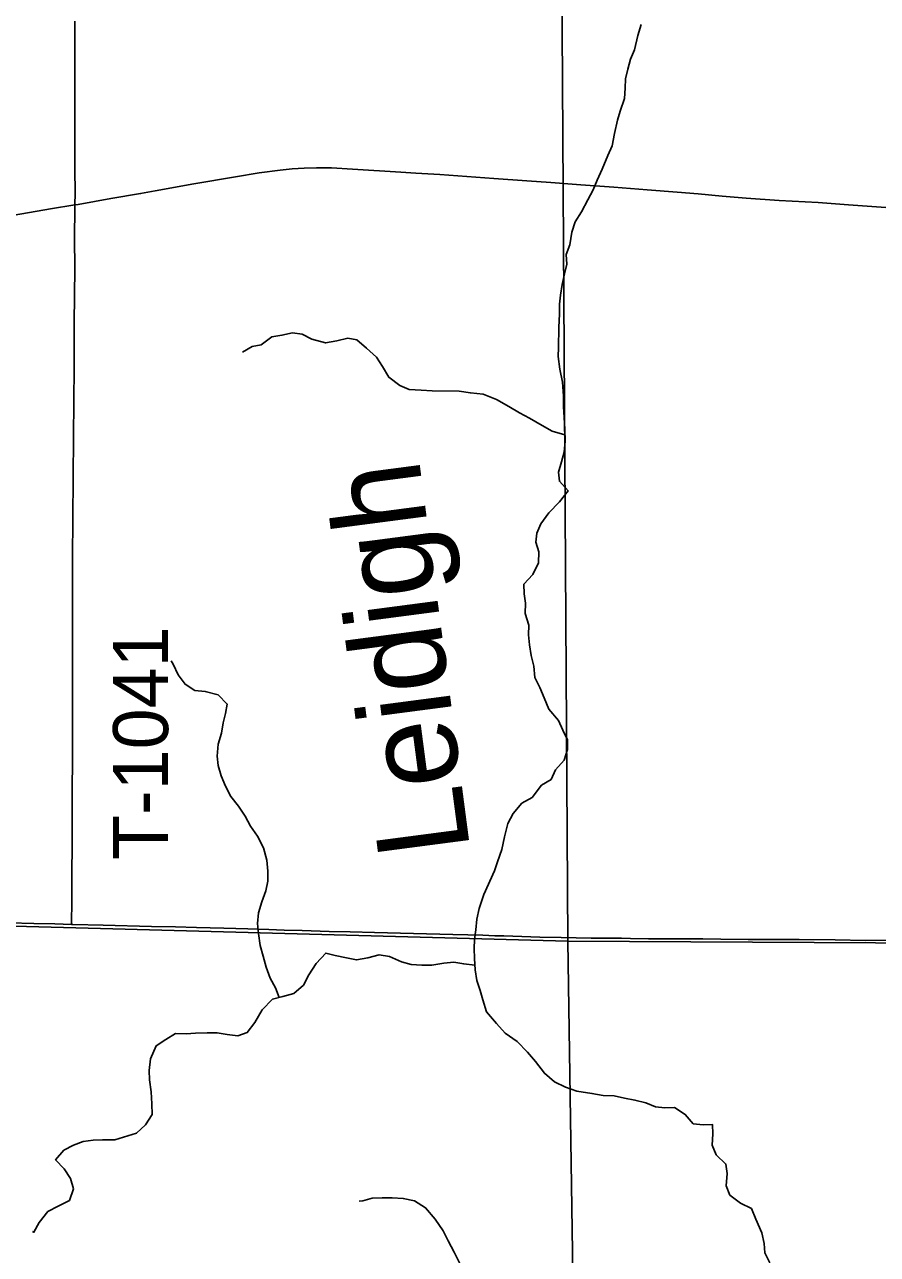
# Model space of a CAD drawing. Extents: x 1874609 to 2204689, y 815661 to 1281160.
# Drawn here: x 2015153 to 2019795, y 1076369 to 1083063 of the extents above; entities that cross this region are included whole.
import ezdxf

# ---------------------------------------------------------------- set-up
doc = ezdxf.new("R2010")
doc.units = 0
for name, color, linetype in [('GM_X_County_Road', 7, 'Continuous'), ('GM_X_Minor_River', 7, 'Continuous'), ('GM_X_Minor_River_Text', 7, 'Continuous'), ('GM_X_Section', 7, 'Continuous'), ('GM_X_Township_Road', 7, 'Continuous'), ('GM_X_Township_Road_Text', 7, 'Continuous')]:
    doc.layers.add(name, color=color, linetype=linetype)

msp = doc.modelspace()

# ---------------------------------------------------------------- linework, layer by layer
at = {"layer": 'GM_X_County_Road'}
for points in [[(2015426.8, 1082081.6), (2015444.7, 1082084.7), (2015622.4, 1082116), (2015784.2, 1082143.6), (2015862.9, 1082157.9), (2016074.7, 1082196.4), (2016301.2, 1082234.7), (2016430.8, 1082255.6), (2016544.6, 1082271.8), (2016610, 1082278.5), (2016675.7, 1082282.5), (2016741.5, 1082284.1), (2016823.7, 1082282.8), (2016938.6, 1082277.1), (2017200.6, 1082260.3), (2017282.4, 1082255.1), (2017413.3, 1082246.6), (2017707.2, 1082224.9), (2017886.9, 1082212.5), (2018017.7, 1082203.1), (2018181.4, 1082191), (2018361.4, 1082178.2), (2018541.3, 1082163.9), (2018704.8, 1082151.5), (2018819.1, 1082141.6), (2018949.7, 1082129.7), (2019080.4, 1082118.5), (2019260.4, 1082106.6), (2019473.5, 1082094.9), (2019637.2, 1082082.7), (2019866.3, 1082065.9)], [(2012702.2, 1081362.5), (2012708, 1081367.4), (2012721.2, 1081376.2), (2012749.7, 1081391.3), (2012779.6, 1081403.9), (2012825.6, 1081420.9), (2012949.6, 1081463.4), (2013150.5, 1081534.9), (2013366.6, 1081612.4), (2013706.1, 1081734.5), (2013830.1, 1081776.8), (2013923.9, 1081806), (2014018.5, 1081832.2), (2014098.2, 1081850.8), (2014226.9, 1081875.3), (2014420.6, 1081909.8), (2014614.7, 1081942.3), (2014970.1, 1082004), (2015293.3, 1082059.6), (2015426.8, 1082081.6)]]:
    msp.add_lwpolyline(points, dxfattribs=at)
at = {"layer": 'GM_X_Minor_River'}
for points in [[(2017919.3, 1080070.8), (2017949.7, 1080132.8), (2017952, 1080193), (2017936.2, 1080245.3), (2017940.5, 1080295.4), (2017962.8, 1080345.5), (2018007.2, 1080405.4), (2018065.6, 1080465.2), (2018112, 1080525.1), (2018064.2, 1080577.6), (2018058.5, 1080627.8), (2018074.8, 1080683.9), (2018091.1, 1080736), (2018095.4, 1080796.2), (2018093.7, 1080860.4), (2018090.1, 1080924.6), (2018086.4, 1080984.9), (2018086.7, 1081041.1), (2018081.1, 1081117.4), (2018067.4, 1081187.7), (2018057.7, 1081256), (2018060, 1081306.2), (2018060.6, 1081414.5), (2018065, 1081488.8), (2018065.3, 1081540.9), (2018069.5, 1081591.1), (2018079.9, 1081649.2), (2018092.2, 1081707.3), (2018104.5, 1081759.4), (2018100.8, 1081811.6), (2018121.1, 1081863.7), (2018131.4, 1081933.9), (2018149.8, 1081989.9), (2018184.1, 1082043.9), (2018218.5, 1082109.9), (2018248.9, 1082163.9), (2018269.2, 1082216), (2018297.5, 1082276), (2018328, 1082350.1), (2018352.3, 1082404.1), (2018364.7, 1082470.2), (2018381.1, 1082542.4), (2018395.4, 1082592.5), (2018417.8, 1082660.6), (2018422.1, 1082716.7), (2018424.4, 1082768.9), (2018436.7, 1082821), (2018451, 1082875.1), (2018473.3, 1082925.1), (2018491.7, 1083003.3), (2018510.1, 1083063.4)], [(2018094.5, 1080830.7), (2018025.6, 1080850.8), (2017969.6, 1080881.3), (2017901.7, 1080921.8), (2017847.8, 1080950.3), (2017789.8, 1080984.8), (2017721.9, 1081023.4), (2017649.9, 1081051.9), (2017579.8, 1081058.4), (2017517.8, 1081068.8), (2017371.5, 1081069.8), (2017311.4, 1081074.2), (2017247.3, 1081076.6), (2017195.4, 1081099), (2017135.5, 1081143.5), (2017101.7, 1081201.9), (2017067.9, 1081252.3), (2017014.1, 1081302.9), (2016962.2, 1081347.3), (2016912.2, 1081355.7), (2016852, 1081342), (2016791.8, 1081330.4), (2016715.8, 1081350.9), (2016663.9, 1081377.4), (2016611.8, 1081385.7), (2016553.6, 1081372.1), (2016499.5, 1081364.4), (2016441.2, 1081320.6), (2016391, 1081310.9), (2016338.8, 1081281.1)], [(2019209.9, 1076323.8), (2019182.1, 1076378.1), (2019178.4, 1076428.3), (2019166.7, 1076486.6), (2019133, 1076561.1), (2019109.2, 1076619.4), (2019049.3, 1076647.9), (2018991.4, 1076692.4), (2018971.6, 1076742.7), (2018978, 1076808.9), (2018970.3, 1076861.1), (2018918.4, 1076911.6), (2018896.7, 1076964), (2018899, 1077026.1), (2018897.3, 1077076.3), (2018847.2, 1077074.6), (2018793.1, 1077079), (2018749.3, 1077131.5), (2018691.4, 1077168), (2018637.3, 1077166.3), (2018587.2, 1077172.6), (2018535.3, 1077195.1), (2018475.2, 1077209.5), (2018419.2, 1077219.9), (2018363.1, 1077232.3), (2018303, 1077234.7), (2018241, 1077245.1), (2018158.9, 1077257.7), (2018096.9, 1077280.2), (2018037, 1077308.6), (2017983.1, 1077355.1), (2017933.3, 1077419.7), (2017891.5, 1077470.1), (2017833.7, 1077528.7), (2017769.9, 1077573.2), (2017722.1, 1077625.7), (2017668.3, 1077690.3), (2017646.6, 1077754.6), (2017632.8, 1077804.9), (2017615.1, 1077859.2), (2017605.4, 1077917.5), (2017601.7, 1077979.7), (2017600, 1078033.9), (2017602.3, 1078084.1), (2017608.5, 1078136.2), (2017614.9, 1078194.3), (2017627.2, 1078252.5), (2017653.6, 1078328.6), (2017710.4, 1078456.6), (2017726.7, 1078506.7), (2017751.1, 1078572.8), (2017765.5, 1078642.9), (2017783.9, 1078715), (2017812.2, 1078769.1), (2017860.6, 1078824.9), (2017916.9, 1078856.7), (2017967.3, 1078922.6), (2018019.6, 1078954.3), (2018043.9, 1079006.4), (2018090.3, 1079060.2), (2018108.6, 1079118.3), (2018108.9, 1079170.5), (2018083.1, 1079222.9), (2018059.3, 1079275.2), (2018007.6, 1079337.7), (2017981.8, 1079398.1), (2017958.1, 1079454.4), (2017930.3, 1079508.8), (2017924.7, 1079571.1), (2017910.9, 1079629.3), (2017901.2, 1079687.6), (2017895.5, 1079741.8), (2017897.8, 1079794), (2017878.1, 1079858.3), (2017880.4, 1079914.5), (2017872.6, 1079964.8), (2017870.9, 1080016.9), (2017919.3, 1080070.8)], [(2016539.1, 1077768.2), (2016518.9, 1077820.1), (2016489.1, 1077872.5), (2016467.4, 1077932.8), (2016451.7, 1077993.1), (2016436, 1078051.4), (2016426.3, 1078115.7), (2016420.6, 1078169.9), (2016426.9, 1078228.1), (2016445.2, 1078288.2), (2016465.6, 1078348.2), (2016477.9, 1078400.3), (2016476.2, 1078454.5), (2016472.5, 1078514.8), (2016452.8, 1078583.1), (2016421.1, 1078645.5), (2016383.3, 1078700), (2016353.5, 1078754.3), (2016317.8, 1078808.8), (2016276, 1078861.2), (2016246.2, 1078917.6), (2016222.5, 1078973.9), (2016206.7, 1079030.2), (2016201, 1079080.4), (2016207.3, 1079146.6), (2016225.7, 1079206.7), (2016234, 1079262.8), (2016246.3, 1079312.9), (2016256.6, 1079365.1), (2016206.7, 1079415.6), (2016136.7, 1079434.1), (2016080.6, 1079438.4), (2016026.7, 1079472.9), (2015988.9, 1079523.3), (2015961.2, 1079581.7), (2015951.3, 1079599.8)], [(2017603.8, 1077943.9), (2017543.4, 1077950), (2017489.4, 1077960.3), (2017435.3, 1077954.7), (2017369.1, 1077943.1), (2017315, 1077943.4), (2017256.9, 1077947.8), (2017204.9, 1077962.2), (2017138.9, 1077990.7), (2017082.9, 1077999.1), (2017020.7, 1077983.4), (2016960.5, 1077971.8), (2016904.5, 1077984.2), (2016844.4, 1077996.6), (2016792.4, 1078009), (2016740, 1077953.1), (2016699.6, 1077891.2), (2016671.3, 1077835.2), (2016618.9, 1077789.4), (2016558.7, 1077773.7), (2016502.6, 1077758), (2016446.2, 1077700.2), (2016405.7, 1077632.2), (2016365.4, 1077576.3), (2016313.2, 1077558.5), (2016255.1, 1077566.9), (2016201.1, 1077575.3), (2016147, 1077575.7), (2016082.9, 1077574.1), (2016032.7, 1077570.4), (2015974.6, 1077570.8), (2015922.4, 1077539), (2015870.1, 1077505.2), (2015837.7, 1077433.1), (2015831.3, 1077371), (2015833.1, 1077318.8), (2015842.7, 1077254.5), (2015846.4, 1077188.3), (2015848.1, 1077130.1), (2015811.7, 1077074.1), (2015761.4, 1077028.3), (2015645, 1076992.9), (2015576.9, 1076993.3), (2015526.8, 1076991.6), (2015472.7, 1076984), (2015418.5, 1076964.2), (2015366.2, 1076936.5), (2015321.9, 1076884.6), (2015367.7, 1076834.1), (2015403.5, 1076781.7), (2015419.2, 1076725.4), (2015396.9, 1076663.4), (2015336.6, 1076631.7), (2015280.3, 1076601.9), (2015231.9, 1076542), (2015203.6, 1076490), (2015195.6, 1076494.1)], [(2017834.9, 1075696), (2017826.3, 1075746.7), (2017798.6, 1075801.1), (2017770.8, 1075859.5), (2017745.1, 1075911.8), (2017677.6, 1076032.6), (2017647.8, 1076091), (2017616.1, 1076145.4), (2017558.6, 1076258.2), (2017524.8, 1076316.6), (2017491.1, 1076381), (2017459.4, 1076443.4), (2017431.6, 1076497.8), (2017387.8, 1076560.3), (2017336.1, 1076622.8), (2017276.2, 1076661.3), (2017214.1, 1076673.8), (2017154, 1076676.2), (2017099.9, 1076676.5), (2017045.8, 1076674.9), (2016993.7, 1076661.1), (2016973.6, 1076659.3)]]:
    msp.add_lwpolyline(points, dxfattribs=at)
at = {"layer": 'GM_X_Section'}
for points in [[(2012556.1, 1083487.7), (2018077.6, 1083333.3), (2018110.7, 1078074.4), (2012685.3, 1078221)], [(2023404.7, 1083328.6), (2023471.9, 1078045.6), (2018110.7, 1078074.4), (2018077.6, 1083333.3)], [(2018110.7, 1078074.4), (2018190, 1072759.5), (2012766.6, 1072920.2), (2012766.5, 1072976.2), (2012685.3, 1078221)], [(2023471.9, 1078045.6), (2023577.1, 1072706.8), (2018190, 1072759.5), (2018110.7, 1078074.4)]]:
    msp.add_lwpolyline(points, close=True, dxfattribs=at)
at = {"layer": 'GM_X_Township_Road'}
for points in [[(2015426.8, 1082081.6), (2015427.6, 1082146.5), (2015426.3, 1082277.7), (2015425.9, 1082425.4), (2015426.5, 1082622.4), (2015427, 1082802.9), (2015426.3, 1082917.8), (2015426.4, 1082966.9), (2015426.5, 1083081.8)], [(2015407.7, 1078165.4), (2015408.3, 1078191.2), (2015410.1, 1078273.3), (2015411, 1078404.6), (2015411.9, 1078634.4), (2015412.3, 1078897), (2015412.9, 1079061.1), (2015413.5, 1079159.5), (2015413.8, 1079340), (2015413.8, 1079520.6), (2015414.4, 1079733.9), (2015414.3, 1079914.4), (2015414.5, 1080160.6), (2015416.5, 1080374), (2015418.4, 1080817.1), (2015420.6, 1081014.1), (2015422.1, 1081194.6), (2015422.3, 1081325.9), (2015423.6, 1081440.7), (2015425.6, 1081736.2), (2015425.1, 1081900.3), (2015426.6, 1082066.8), (2015426.8, 1082081.6)], [(2012697.1, 1078241.8), (2012740.6, 1078240.5), (2012872.1, 1078236.7), (2012986.9, 1078233.3), (2013183.9, 1078228.5), (2013413.7, 1078222.5), (2013660, 1078215.1), (2013840.6, 1078210.3), (2013988.3, 1078207.1), (2014119.6, 1078204.2), (2014218.1, 1078201.7), (2014530, 1078192), (2014710.5, 1078185.9), (2014907.5, 1078179.3), (2015071.6, 1078174.6), (2015202.9, 1078170.6), (2015317.8, 1078167.7), (2015407.7, 1078165.4)], [(2015407.7, 1078165.4), (2015416.3, 1078165.2), (2015580.5, 1078161.2), (2015843.1, 1078154.7), (2015974.4, 1078151.7), (2016089.4, 1078148.1), (2016236.9, 1078144.2), (2016368.2, 1078140.9), (2016483.1, 1078137), (2016565.1, 1078134.2), (2016663.6, 1078131.4), (2016712.8, 1078130.2), (2016811.1, 1078127.5), (2016925.9, 1078124.5), (2017057.2, 1078121.2), (2017270.6, 1078115.1), (2017484, 1078110), (2017648.2, 1078106), (2017713.6, 1078103.8), (2017762, 1078102.7), (2017958.5, 1078096.5), (2018073.4, 1078093.6), (2018237.5, 1078090.9), (2018401.8, 1078090), (2018451, 1078089.3), (2018549.4, 1078086.6), (2018647.8, 1078086), (2018844.9, 1078086.4), (2018943.4, 1078085.6), (2019091.1, 1078083.9), (2019188.9, 1078083.6), (2019369.1, 1078083.3), (2019566.2, 1078080.8), (2019730.4, 1078078.3), (2019878.1, 1078079.3)]]:
    msp.add_lwpolyline(points, dxfattribs=at)

# ---------------------------------------------------------------- texts
at = {"layer": 'GM_X_Minor_River_Text'}
msp.add_text('Leidigh', height=500.21, rotation=97.47463, dxfattribs=at).set_placement((2017579.4, 1078570.2))
at = {"layer": 'GM_X_Township_Road_Text'}
msp.add_text('T-1041', height=300, rotation=90, dxfattribs=at).set_placement((2015934.3, 1078516.4))

doc.saveas('drawing.dxf')
